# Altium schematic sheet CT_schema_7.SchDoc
size 402 x 220 mm
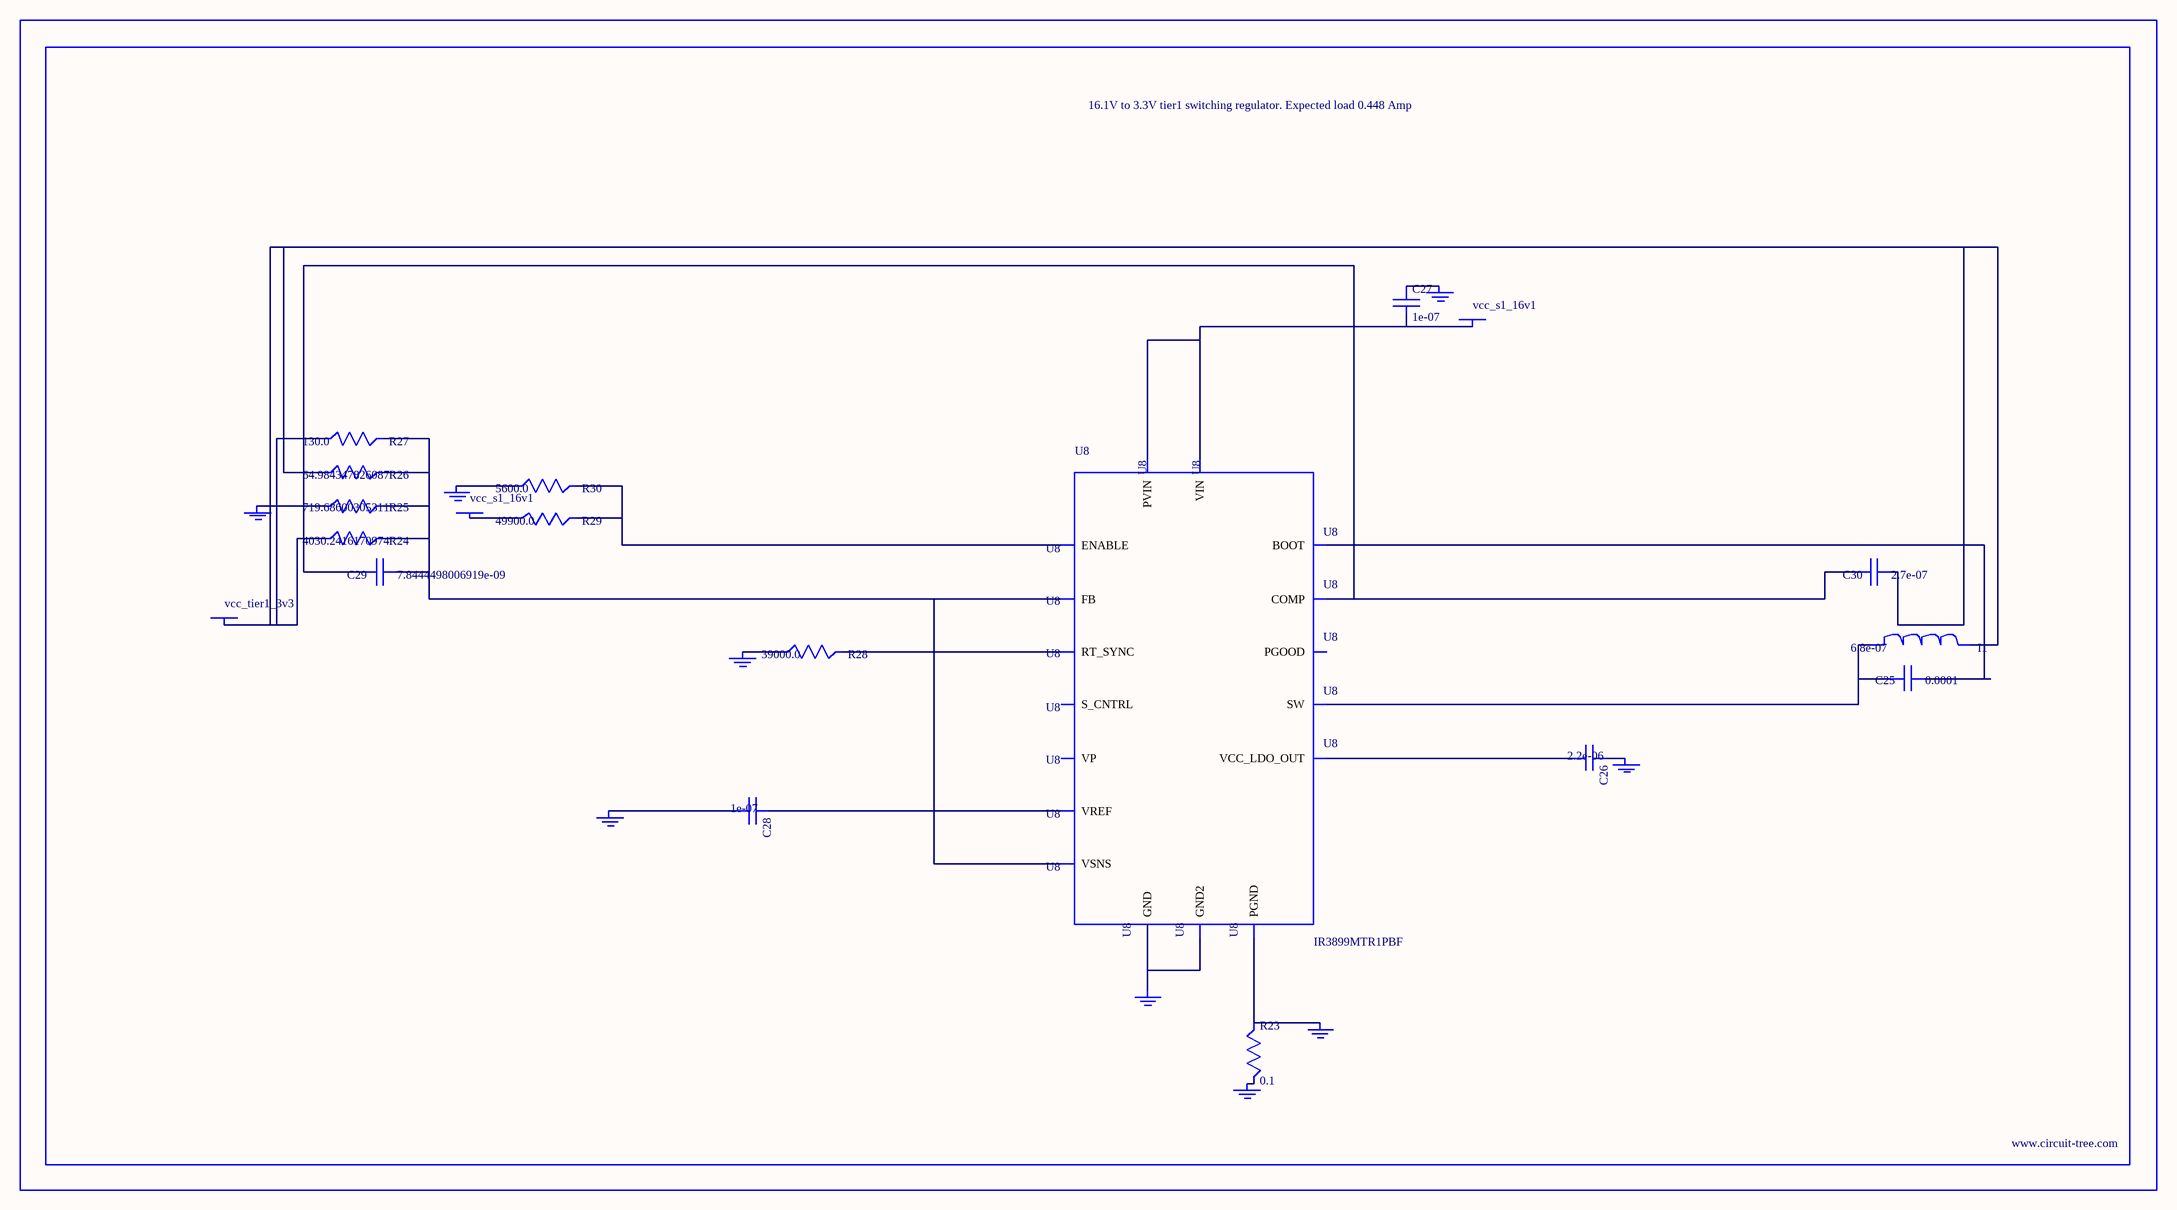
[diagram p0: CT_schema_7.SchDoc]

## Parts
BORDER6  (no value)
C25  0.0001  [C1210]
C26  2.2e-06  [C0603]
C27  1e-07  [C0402]
C28  1e-07  [C0402]
C29  7.8444498006919e-09  [R0603]
C30  2.7e-07  [C0603]
GND_INSTANCE_6_0  (no value)
GND_INSTANCE_6_1  (no value)
GND_INSTANCE_6_2  (no value)
GND_INSTANCE_6_3  (no value)
GND_INSTANCE_6_4  (no value)
GND_INSTANCE_6_5  (no value)
GND_INSTANCE_6_6  (no value)
GND_INSTANCE_6_7  (no value)
GND_INSTANCE_6_8  (no value)
I1  6.8e-07  [IND25X25CZ]
POWER_INSTANCE_6_0  vcc_s1_16v1
POWER_INSTANCE_6_1  vcc_s1_16v1
POWER_INSTANCE_6_2  vcc_tier1_3v3
R23  0.1  [R0603]
R24  4030.2416170974  [R0603]
R25  719.68600305311  [R0603]
R26  64.984347826087  [R0603]
R27  130.0  [R0603]
R28  39000.0  [R0603]
R29  49900.0  [R0603]
R30  5600.0  [R0603]
U8  IR3899MTR1PBF  [IR3899MTR1PBF]

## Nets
NetC25_1: C25.1 U8.14(BOOT)
NetC25_2: C25.2 I1.1 U8.12(SW)
NetC26_1: C26.1 GND_INSTANCE_6_4.0(GND)
NetC26_2: C26.2 U8.10(VCC_LDO_OUT)
NetC27_1: C27.1 GND_INSTANCE_6_3.0(GND)
NetC27_2: C27.2 POWER_INSTANCE_6_0.0(PWR) U8.9(VIN) U8.13(PVIN)
NetC28_1: C28.1 U8.2(VREF)
NetC28_2: C28.2 GND_INSTANCE_6_1.0(GND)
NetC29_1: C29.1 R24.2 R25.2 R26.2 R27.2 U8.1(FB) U8.8(VSNS)
NetC29_2: C29.2 C30.2 U8.3(COMP)
NetC30_1: C30.1 I1.2 POWER_INSTANCE_6_2.0(PWR) R24.1 R26.1 R27.1
NetGND_INSTANCE_6_0_0: GND_INSTANCE_6_0.0(GND) R25.1
NetGND_INSTANCE_6_2_0: GND_INSTANCE_6_2.0(GND) R28.1
NetGND_INSTANCE_6_5_0: GND_INSTANCE_6_5.0(GND) R23.2
NetGND_INSTANCE_6_6_0: GND_INSTANCE_6_6.0(GND) R23.1 U8.11(PGND)
NetGND_INSTANCE_6_7_0: GND_INSTANCE_6_7.0(GND) R30.1
NetGND_INSTANCE_6_8_0: GND_INSTANCE_6_8.0(GND) U8.4(GND) U8.17(GND2)
NetPOWER_INSTANCE_6_1_0: POWER_INSTANCE_6_1.0(PWR) R29.1
NetR28_2: R28.2 U8.5(RT_SYNC)
NetR29_2: R29.2 R30.2 U8.15(ENABLE)

Not connected (* = marked no-connect by the designer): U8 6(S_CNTRL) 7(PGOOD) 16(VP)

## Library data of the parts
BORDER6 = BORDER_PAGE6
C25 = GRM32ER61A107ME20L
C26 = C0603C225K8RACTU
C27 C28 = C0402C104K3RACTU
C29 = C29
C30 = C0603C274K3RAC
GND_INSTANCE_6_0-GND_INSTANCE_6_8 = GND
I1 = IHLP2525CZERR68M01
POWER_INSTANCE_6_0-POWER_INSTANCE_6_2 = PWR
R23 = ERJ-3RSFR10V
R24 = R24
R25 = R25
R26 = R26
R27 = RC0603JR-07130RL
R28 = RC0603JR-0739KL
R29 = RC0603FR-0749K9
R30 = RC0603JR-075K6L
